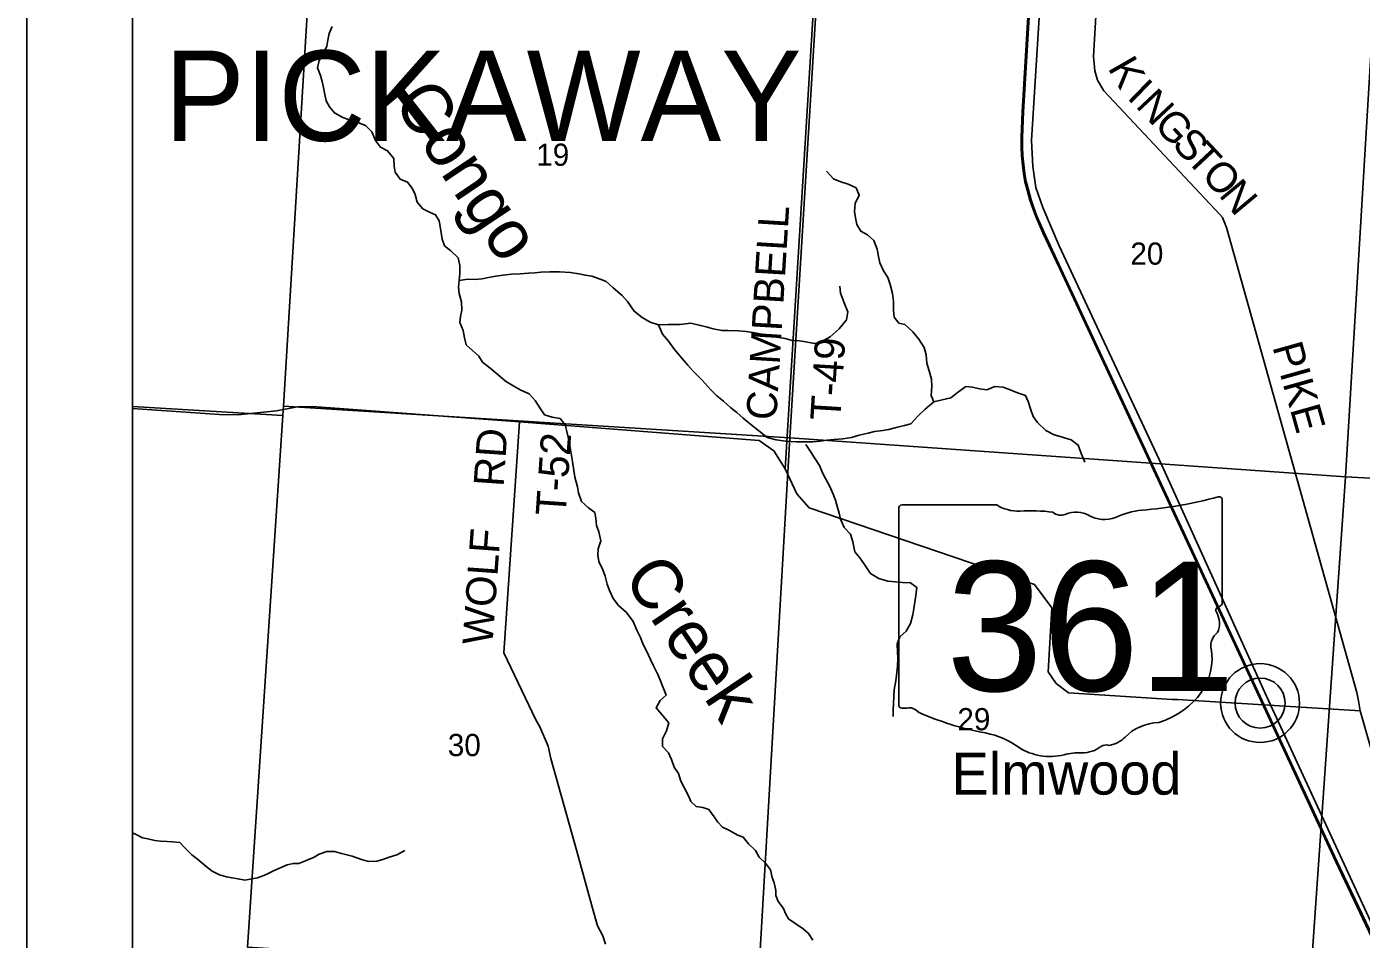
# Model space of a CAD drawing. Extents: x 0 to 42.5, y 0 to 22.
# Drawn here: x 2 to 3.26, y 16.524 to 17.385 of the extents above; entities that cross this region are included whole.
import ezdxf

# ---------------------------------------------------------------- set-up
doc = ezdxf.new("R2010")
doc.units = 0
for name, color, linetype in [('GM_X_County_Road', 7, 'Continuous'), ('GM_X_County_Road_Text', 7, 'Continuous'), ('GM_X_Interchange_Ramps', 7, 'Continuous'), ('GM_X_Minor_River', 7, 'Continuous'), ('GM_X_Minor_River_Text', 7, 'Continuous'), ('GM_X_Rail_Line', 7, 'Continuous'), ('GM_X_Section', 7, 'Continuous'), ('GM_X_Section_Text', 7, 'Continuous'), ('GM_X_State_Location', 7, 'Continuous'), ('GM_X_State_Route', 7, 'Continuous'), ('GM_X_State_Shield', 7, 'Continuous'), ('GM_X_Township_Road', 7, 'Continuous'), ('GM_X_Township_Road_Text', 7, 'Continuous'), ('GM_X_Township_Text', 7, 'Continuous'), ('GM_X_Unincorporated', 7, 'Continuous'), ('GM_X_Unincorporated_Location', 7, 'Continuous'), ('GM_X_Unincorporated_Text', 7, 'Continuous'), ('SH_Cut_Line', 7, 'Continuous'), ('SH_Data', 7, 'Continuous')]:
    doc.layers.add(name, color=color, linetype=linetype)

msp = doc.modelspace()

# ---------------------------------------------------------------- linework, layer by layer
at = {"layer": 'GM_X_County_Road'}
msp.add_lwpolyline([(3.0446, 18.0046), (3.039, 17.909), (3.0079, 17.3736), (3.007, 17.3571), (3.0082, 17.3435), (3.0108, 17.3349), (3.0166, 17.3248), (3.1262, 17.2079), (3.1288, 17.2053), (3.1325, 17.1958), (3.2557, 16.7571), (3.257, 16.7491), (3.2586, 16.7395)], dxfattribs=at)
at = {"layer": 'GM_X_Interchange_Ramps'}
msp.add_lwpolyline([(3.3708, 18.9861), (3.12, 19.001), (2.9496, 19.012), (2.741, 19.0247), (2.6729, 19.0297), (2.6231, 19.0318), (2.5272, 19.0385), (2.4885, 19.0403), (2.4656, 19.0429), (2.4593, 19.0431), (2.3672, 19.046), (2.1, 19.059), (2.1, 16.0076)], dxfattribs=at)
at = {"layer": 'GM_X_Minor_River'}
for points in [[(2.2797, 17.3596), (2.2833, 17.367), (2.2843, 17.3725), (2.2855, 17.379), (2.2882, 17.3854)], [(2.606, 16.7282), (2.5941, 16.7426), (2.5981, 16.7495), (2.6036, 16.7544), (2.6006, 16.7622), (2.5982, 16.7681), (2.5956, 16.7738), (2.5913, 16.7826), (2.5887, 16.7881), (2.5849, 16.7963), (2.5817, 16.803), (2.5793, 16.8087), (2.576, 16.8159), (2.5724, 16.8239), (2.5662, 16.8323), (2.5587, 16.839), (2.5536, 16.8457), (2.5502, 16.8533), (2.5478, 16.8591), (2.5459, 16.8667), (2.5439, 16.8728), (2.54, 16.8806), (2.5392, 16.8867), (2.5395, 16.8926), (2.5418, 16.9), (2.5401, 16.9087), (2.5377, 16.9144), (2.5372, 16.9213), (2.5363, 16.9268), (2.5302, 16.9312), (2.5236, 16.9373), (2.521, 16.9453), (2.5199, 16.951), (2.5175, 16.9602), (2.5151, 16.975), (2.5139, 16.9824), (2.5131, 16.9881), (2.5117, 16.9954), (2.5098, 17.0034), (2.5082, 17.0094), (2.5035, 17.0154), (2.4959, 17.0169), (2.4889, 17.0191), (2.4849, 17.0248), (2.4799, 17.0324), (2.4742, 17.0387), (2.4665, 17.0424), (2.4597, 17.0459), (2.4519, 17.0507), (2.445, 17.0568), (2.4374, 17.0629), (2.4301, 17.0687), (2.4269, 17.0744), (2.4209, 17.0796), (2.4148, 17.0851), (2.4132, 17.0916), (2.4121, 17.0986), (2.4087, 17.1061), (2.4095, 17.1119), (2.4107, 17.1178), (2.4105, 17.1256), (2.4081, 17.1334), (2.4076, 17.1395), (2.4082, 17.1458), (2.409, 17.1524), (2.4088, 17.16), (2.4074, 17.1671), (2.4004, 17.1738), (2.3944, 17.1786), (2.3923, 17.1848), (2.391, 17.1928), (2.3894, 17.2022), (2.386, 17.2077), (2.3802, 17.2104), (2.3739, 17.2135), (2.3687, 17.2198), (2.3666, 17.227), (2.3638, 17.2329), (2.3595, 17.2386), (2.3525, 17.2415), (2.3478, 17.248), (2.3469, 17.2537), (2.3467, 17.2608), (2.3407, 17.2682), (2.3339, 17.2715), (2.3294, 17.278), (2.3257, 17.2862), (2.3198, 17.2919), (2.3126, 17.2948), (2.3062, 17.2968), (2.2985, 17.2997), (2.2905, 17.3039), (2.2858, 17.3098), (2.2826, 17.3153), (2.2813, 17.3212), (2.2801, 17.3279), (2.2788, 17.3336), (2.2773, 17.3391), (2.2745, 17.3464), (2.2761, 17.3534), (2.2797, 17.3596)], [(2.8562, 17.0312), (2.8539, 17.0373), (2.8544, 17.0458), (2.8542, 17.0527), (2.8518, 17.0605), (2.8498, 17.0679), (2.8489, 17.0755), (2.847, 17.0826), (2.842, 17.0904), (2.8365, 17.0973), (2.829, 17.1041), (2.8231, 17.1055), (2.8188, 17.1112), (2.8181, 17.1173), (2.8181, 17.1259), (2.8174, 17.1335), (2.8152, 17.1421), (2.8129, 17.1485), (2.8088, 17.155), (2.8052, 17.1623), (2.804, 17.1685), (2.8027, 17.1752), (2.7995, 17.1836), (2.7935, 17.1888), (2.7874, 17.1922), (2.7835, 17.1985), (2.7824, 17.2048), (2.7813, 17.2109), (2.7819, 17.2183), (2.7859, 17.2262), (2.7829, 17.2331), (2.7754, 17.2368), (2.7684, 17.2389), (2.7616, 17.2418), (2.7548, 17.2491)], [(2.4082, 17.1458), (2.4163, 17.1471), (2.4233, 17.1468), (2.43, 17.1474), (2.4374, 17.1488), (2.4429, 17.1499), (2.4497, 17.1508), (2.4575, 17.1517), (2.4658, 17.1521), (2.4738, 17.1526), (2.4795, 17.1531), (2.4853, 17.1535), (2.4939, 17.1538), (2.5028, 17.1539), (2.5134, 17.1533), (2.5212, 17.1521), (2.5274, 17.1507), (2.5333, 17.1497), (2.5412, 17.147), (2.5471, 17.1447), (2.5537, 17.139), (2.562, 17.1315), (2.567, 17.1258), (2.5734, 17.1168), (2.581, 17.1108), (2.5885, 17.1066), (2.5965, 17.1039), (2.6056, 17.1042), (2.6112, 17.1042), (2.6169, 17.1043), (2.627, 17.1054), (2.6349, 17.1037), (2.6415, 17.1021), (2.648, 17.1), (2.6561, 17.0986), (2.6618, 17.0986), (2.672, 17.0983), (2.6792, 17.0977), (2.6853, 17.0967), (2.7012, 17.0939), (2.7099, 17.092), (2.7158, 17.091), (2.7224, 17.0892), (2.7294, 17.0888), (2.7354, 17.0878), (2.7436, 17.0863), (2.7493, 17.0875), (2.7584, 17.0926), (2.767, 17.1002), (2.7737, 17.1087), (2.775, 17.1163), (2.7722, 17.1231), (2.7683, 17.1338), (2.7674, 17.1405)], [(2.5965, 17.1039), (2.6, 17.0951), (2.6058, 17.0885), (2.6115, 17.0806), (2.6184, 17.0724), (2.6241, 17.0659), (2.6292, 17.0602), (2.6373, 17.052), (2.6459, 17.0426), (2.6514, 17.037), (2.6576, 17.0319), (2.6646, 17.0257), (2.6702, 17.0211), (2.6763, 17.0158), (2.6836, 17.0099), (2.6908, 17.0043), (2.6991, 16.9976), (2.7074, 16.9953), (2.7163, 16.9942), (2.7267, 16.9934), (2.7324, 16.9934), (2.7421, 16.9935), (2.7489, 16.9942), (2.7553, 16.995), (2.7622, 16.9957), (2.7703, 16.9964), (2.7787, 16.9977), (2.7859, 16.9999), (2.7944, 17.0017), (2.8003, 17.0034), (2.8081, 17.0043), (2.8138, 17.0052), (2.8219, 17.0073), (2.8286, 17.0089), (2.8345, 17.0104), (2.8415, 17.018), (2.848, 17.0244), (2.8562, 17.0312), (2.864, 17.033), (2.8723, 17.0349), (2.8784, 17.0396), (2.8864, 17.0458), (2.8928, 17.0452), (2.8993, 17.0436), (2.9063, 17.0427), (2.9137, 17.0458), (2.9216, 17.045), (2.9298, 17.0421), (2.9354, 17.0396), (2.9428, 17.0371), (2.9452, 17.0316), (2.9477, 17.0238), (2.9501, 17.0175), (2.954, 17.0118), (2.9621, 17.0043), (2.9697, 17.0001), (2.9756, 16.9985), (2.9858, 16.9954), (2.9926, 16.9904), (2.995, 16.9834), (2.9987, 16.9744)], [(2.8178, 16.7342), (2.8178, 16.7405), (2.8183, 16.7467), (2.8185, 16.753), (2.8189, 16.7595), (2.8203, 16.768), (2.8213, 16.7758), (2.8221, 16.7817), (2.8223, 16.7893), (2.822, 16.795), (2.8216, 16.8028), (2.8243, 16.8094), (2.8302, 16.8149), (2.8344, 16.8221), (2.8364, 16.8304), (2.8378, 16.8382), (2.839, 16.8464), (2.8401, 16.8561), (2.8343, 16.8603), (2.8267, 16.8609), (2.8201, 16.8615), (2.8127, 16.8621), (2.8042, 16.8646), (2.7966, 16.8694), (2.7908, 16.8777), (2.7863, 16.8841), (2.7816, 16.8897), (2.7798, 16.8992), (2.7775, 16.9064), (2.7715, 16.9127), (2.7683, 16.9204), (2.7669, 16.9261), (2.7652, 16.9316), (2.7633, 16.9385), (2.7613, 16.944), (2.7581, 16.9514), (2.754, 16.9589), (2.7512, 16.9644), (2.7482, 16.9711), (2.7437, 16.9783), (2.7397, 16.9844), (2.7356, 16.9911)], [(2.606, 16.7282), (2.604, 16.7208), (2.6001, 16.7131), (2.6002, 16.706), (2.6057, 16.6999), (2.6085, 16.6936), (2.6112, 16.6865), (2.6151, 16.6806), (2.6175, 16.6733), (2.621, 16.6666), (2.6251, 16.6589), (2.627, 16.654), (2.632, 16.6495), (2.6383, 16.6483), (2.644, 16.6465), (2.649, 16.6396), (2.6524, 16.6346), (2.6569, 16.6298), (2.6627, 16.6271), (2.6714, 16.6222), (2.6763, 16.6203), (2.6812, 16.6141), (2.688, 16.6079), (2.6915, 16.6014), (2.6973, 16.5958), (2.702, 16.5895), (2.7036, 16.5824), (2.7056, 16.5773), (2.7071, 16.5702), (2.7072, 16.5653), (2.7094, 16.5597), (2.7145, 16.5532), (2.7161, 16.5484), (2.7191, 16.5434), (2.7251, 16.5392), (2.7328, 16.534), (2.7381, 16.5295), (2.742, 16.5232)], [(2.1, 16.6245), (2.1032, 16.623), (2.1092, 16.6199), (2.1145, 16.6188), (2.121, 16.6174), (2.1263, 16.6166), (2.1327, 16.6163), (2.1379, 16.6161), (2.1445, 16.6154), (2.1497, 16.61), (2.1559, 16.6039), (2.1612, 16.5998), (2.1693, 16.5927), (2.1751, 16.5884), (2.1819, 16.5849), (2.1887, 16.5829), (2.1939, 16.5819), (2.2011, 16.5807), (2.2058, 16.58), (2.2109, 16.5807), (2.218, 16.5822), (2.2254, 16.5849), (2.2331, 16.5888), (2.246, 16.5944), (2.2514, 16.5955), (2.2569, 16.5956), (2.2632, 16.598), (2.2714, 16.6017), (2.2762, 16.6045), (2.2832, 16.6069), (2.2906, 16.6068), (2.2973, 16.605), (2.3022, 16.6038), (2.3073, 16.6024), (2.316, 16.5992), (2.3226, 16.5976), (2.3304, 16.5979), (2.3363, 16.5992), (2.3422, 16.6014), (2.3493, 16.6039), (2.3569, 16.6078)]]:
    msp.add_lwpolyline(points, dxfattribs=at)
at = {"layer": 'GM_X_Rail_Line'}
for points in [[(3.3399, 16.3868), (3.1703, 16.7536), (3.0714, 16.9716), (3.0122, 17.0975), (2.9745, 17.1785), (2.959, 17.2147), (2.9527, 17.2334), (2.9497, 17.2534), (2.9485, 17.278), (2.9623, 17.5), (2.9768, 17.7621), (2.9806, 17.8408), (2.977, 17.8698), (2.9731, 17.8901), (2.9655, 17.9182), (2.905, 18.0749), (2.8682, 18.17)], [(3.2698, 16.5254), (3.2357, 16.5973), (3.176, 16.7257), (3.0339, 17.0305), (2.9774, 17.1519), (2.9593, 17.1906), (2.9525, 17.2061), (2.9496, 17.2138), (2.947, 17.2215), (2.9443, 17.2309), (2.9423, 17.2389), (2.9409, 17.2467), (2.9399, 17.2547), (2.9391, 17.2633), (2.9388, 17.2723), (2.9388, 17.2809), (2.9398, 17.3049), (2.9469, 17.4266)], [(3.2709, 16.5259), (3.2368, 16.5979), (3.177, 16.7262), (3.035, 17.031), (2.9785, 17.1524), (2.9604, 17.1911), (2.9536, 17.2066), (2.9507, 17.2142), (2.9482, 17.2218), (2.9455, 17.2312), (2.9435, 17.2392), (2.9421, 17.2469), (2.9411, 17.2549), (2.9403, 17.2633), (2.94, 17.2723), (2.94, 17.2808), (2.941, 17.3048), (2.9481, 17.4265)]]:
    msp.add_lwpolyline(points, dxfattribs=at)
at = {"layer": 'GM_X_Section'}
for points in [[(2.2724, 17.5223), (2.2739, 17.5443), (2.7519, 17.512), (2.7205, 16.9974), (2.2424, 17.0272)], [(2.7519, 17.512), (3.276, 17.4794), (3.2447, 16.9606), (2.7205, 16.9974)], [(3.276, 17.4794), (3.7924, 17.4474), (3.7577, 16.9327), (3.2447, 16.9606)], [(2.2424, 17.0272), (2.7205, 16.9974), (2.6908, 16.4865), (2.2084, 16.5167), (2.2418, 17.0185)], [(3.2447, 16.9606), (3.2094, 16.4499), (2.6908, 16.4865), (2.7205, 16.9974)], [(3.7577, 16.9327), (3.7198, 16.4108), (3.2094, 16.4499), (3.2447, 16.9606)]]:
    msp.add_lwpolyline(points, close=True, dxfattribs=at)
at = {"layer": 'GM_X_State_Route'}
for points in [[(2.1, 17.025), (2.1821, 17.0193), (2.1993, 17.0189), (2.2357, 17.0228), (2.2556, 17.0266), (2.2699, 17.0269), (2.4651, 17.0123), (2.6914, 16.9949), (2.7051, 16.9851), (2.7159, 16.9681), (2.7269, 16.9445), (2.7386, 16.9313), (2.9512, 16.859), (2.9677, 16.837), (2.9643, 16.7766), (2.9718, 16.7654), (2.9834, 16.7565), (3.0812, 16.7505), (3.0863, 16.7502)], [(3.0863, 16.7502), (3.2586, 16.7395), (3.2705, 16.6979), (3.308, 16.5664), (3.3173, 16.5434), (3.7269, 15.9734)]]:
    msp.add_lwpolyline(points, dxfattribs=at)
at = {"layer": 'GM_X_State_Shield'}
for p, q in [((2.9156, 16.934), (2.8261, 16.934)), ((3.1285, 16.8416), (3.1285, 16.9386)), ((2.8231, 16.9308), (2.8231, 16.7454)), ((3.1285, 16.8416), (3.1285, 16.8416))]:
    msp.add_line(p, q, dxfattribs=at)
for centre, major_axis, start_param, end_param in [((2.8266, 16.9312), (0.00354, 0), 1.712693, 3.28349), ((2.9369, 16.9555), (0.0343, 0), 4.042523, 4.731795), ((3.0197, 17.1868), (0.3239, 0), 4.814394, 5.042369), ((3.1252, 16.939), (0.0034, 0), 6.141152, 7.989035), ((2.9483, 16.8299), (0.1232, 0), 1.404758, 1.657858), ((2.9762, 16.9322), (0.0099, 0), 3.836095, 5.185415), ((2.9908, 16.9107), (0.0206, 0), 0.950623, 2.079405), ((3.0173, 16.9401), (0.0248, 0), 4.081561, 5.145723), ((3.0611, 16.8773), (0.0652, 0), 1.699011, 2.107814), ((3.1278, 16.8345), (0.00526, 0), 1.883978, 3.671073), ((3.0943, 16.8222), (0.0316, 0), 5.934695, 6.695948), ((3.1249, 16.8412), (0.00364, 0), 5.05454, 6.418171), ((3.1407, 16.801), (0.023, 0), 2.387724, 3.262537), ((3.0379, 16.7886), (0.081, 0), 5.101752, 6.440018), ((2.8267, 16.7449), (0.00357, 0), 3.00124, 4.508301), ((2.8272, 16.7639), (0.0272, 0), 4.665946, 4.897461), ((2.8328, 16.7347), (0.00982, 0), 0.519207, 1.627899), ((2.9568, 16.9013), (0.2339, 0), 4.195997, 4.488961), ((2.8871, 16.662), (0.0732, 0), 0.823519, 1.323587), ((3.0721, 16.6933), (0.0444, 0), 1.647645, 2.488434), ((2.9662, 16.7337), (0.0464, 0), 4.026481, 4.996735), ((2.9964, 16.7198), (0.0247, 0), 4.691044, 5.507374), ((3.0188, 16.7019), (0.00697, 0), 1.147584, 2.315152), ((3.0158, 16.7274), (0.0262, 0), 4.937069, 5.64225), ((2.993, 16.6696), (0.0382, 0), 1.495662, 1.94098)]:
    msp.add_ellipse(centre, major_axis=major_axis, ratio=0.8, start_param=start_param, end_param=end_param, dxfattribs=at)
at = {"layer": 'GM_X_Township_Road'}
msp.add_line((2.7159, 16.9681), (2.7668, 17.8), dxfattribs=at)
msp.add_lwpolyline([(2.4651, 17.0123), (2.4504, 16.7944), (2.4805, 16.731), (2.4844, 16.7246), (2.4923, 16.7064), (2.4948, 16.6946), (2.5193, 16.6072), (2.534, 16.5533), (2.5389, 16.5366), (2.5439, 16.5273), (2.5464, 16.5195)], dxfattribs=at)
at = {"layer": 'GM_X_Unincorporated'}
msp.add_lwpolyline([(2.1, 17.533), (2.1, 17.0269), (2.2418, 17.0185), (2.2424, 17.0272), (2.2724, 17.5223)], close=True, dxfattribs=at)
for radius in [0.0372, 0.0236]:
    msp.add_circle((3.1642, 16.747), radius, dxfattribs=at)
at = {"layer": 'GM_X_Unincorporated_Location'}
msp.add_line((3.1642, 16.747), (3.1642, 16.747), dxfattribs=at)
at = {"layer": 'SH_Cut_Line'}
msp.add_lwpolyline([(5.4888, 19.405), (5.5006, 19.5525), (5.5106, 19.6694), (5.5156, 19.736), (5.5253, 19.8538), (5.5354, 19.9847), (5.5461, 20.1166), (5.5647, 20.3456), (5.5656, 20.355), (5.5659, 20.3573), (5.6025, 20.8068), (5.6096, 20.9), (2.1, 20.9), (2.1, 16.0076)], dxfattribs=at)
at = {"layer": 'SH_Data'}
for p, q in [((2, 21), (2, 14)), ((2.1, 20.9), (2.1, 14.1))]:
    msp.add_line(p, q, dxfattribs=at)

# ---------------------------------------------------------------- texts
at = {"layer": 'GM_X_County_Road_Text'}
for s, height, rotation, p in [('K', 0.0284, 299.8258, (3.02, 17.3464)), ('I', 0.0284, 315.91, (3.0377, 17.3179)), ('N', 0.0284, 313.1747, (3.0459, 17.31)), ('G', 0.0284, 313.1756, (3.063, 17.2918)), ('S', 0.0284, 313.1761, (3.0801, 17.2735)), ('T', 0.0284, 313.1769, (3.0932, 17.2596)), ('O', 0.0284, 313.1335, (3.1077, 17.2441)), ('N', 0.0284, 309.8182, (3.1245, 17.2261)), ('PIKE', 0.02841, 285.6898, (3.1757, 17.0833))]:
    msp.add_text(s, height=height, rotation=rotation, dxfattribs=at).set_placement(p)
at = {"layer": 'GM_X_Minor_River_Text'}
for s, rotation, p in [('Congo', 303.8565, (2.3449, 17.3146)), ('Creek', 303.8575, (2.5621, 16.866))]:
    msp.add_text(s, height=0.04735, rotation=rotation, dxfattribs=at).set_placement(p)
at = {"layer": 'GM_X_Section_Text'}
for s, p in [('19', (2.481, 17.254)), ('20', (3.0418, 17.1607)), ('29', (2.8785, 16.7213)), ('30', (2.3975, 16.6969))]:
    msp.add_text(s, height=0.02093, rotation=0, dxfattribs=at).set_placement(p)
at = {"layer": 'GM_X_State_Location'}
for s in ['s', 'r']:
    msp.add_text(s, height=0.0000947, dxfattribs=at).set_placement((2.968, 16.7702))
msp.add_text('361', height=0.0000947, rotation=0, dxfattribs=at).set_placement((2.9345, 16.7633))
at = {"layer": 'GM_X_State_Shield'}
msp.add_text('361', height=0.12217, dxfattribs=at).set_placement((2.8681, 16.7584))
at = {"layer": 'GM_X_Township_Road_Text'}
for s, rotation, p in [('CAMPBELL', 86.5122, (2.7075, 17.0134)), ('T-49', 86.4683, (2.7679, 17.013)), ('RD', 86.0209, (2.4501, 16.9506)), ('T-52', 86.0909, (2.5087, 16.9231)), ('WOLF', 85.8794, (2.4396, 16.8011))]:
    msp.add_text(s, height=0.02841, rotation=rotation, dxfattribs=at).set_placement(p)
at = {"layer": 'GM_X_Township_Text'}
msp.add_text('PICKAWAY', height=0.08523, rotation=0, dxfattribs=at).set_placement((2.1299, 17.2775))
at = {"layer": 'GM_X_Unincorporated_Text'}
msp.add_text('Elmwood', height=0.03949, rotation=0, dxfattribs=at).set_placement((2.8729, 16.6606))

doc.saveas('drawing.dxf')
